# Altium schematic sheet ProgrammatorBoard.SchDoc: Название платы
size 209 x 297 mm; ApprovedBy: Рогов; CheckedBy: Фамилия проверяющего; DrawnBy: Фамилия разработчика; DocumentNumber: Введите номер платы + Э3; SheetNumber: пусто если всего 1, в остальных случаях 1; SheetTotal: количество листов; PageSetup: Record=PageOptions¦CenterHorizontal=True¦CenterVertical=True¦PrintScale=0.94¦XCorrection=1.00¦YCorrection=1.00¦PrintKind=2¦BorderSize=5000000¦LeftOffset=0¦BottomOffset=0¦Orientation=1¦PaperLength=2970¦PaperWidth=2100¦Scale=100¦PaperSource=7¦PrintQuality=600¦MediaType=1¦DitherType=10¦PaperKind=A4¦PrintScaleMode=1; Title1str: (вторая строка при необходимости); DocumentType: Тип схемы; Format: A4
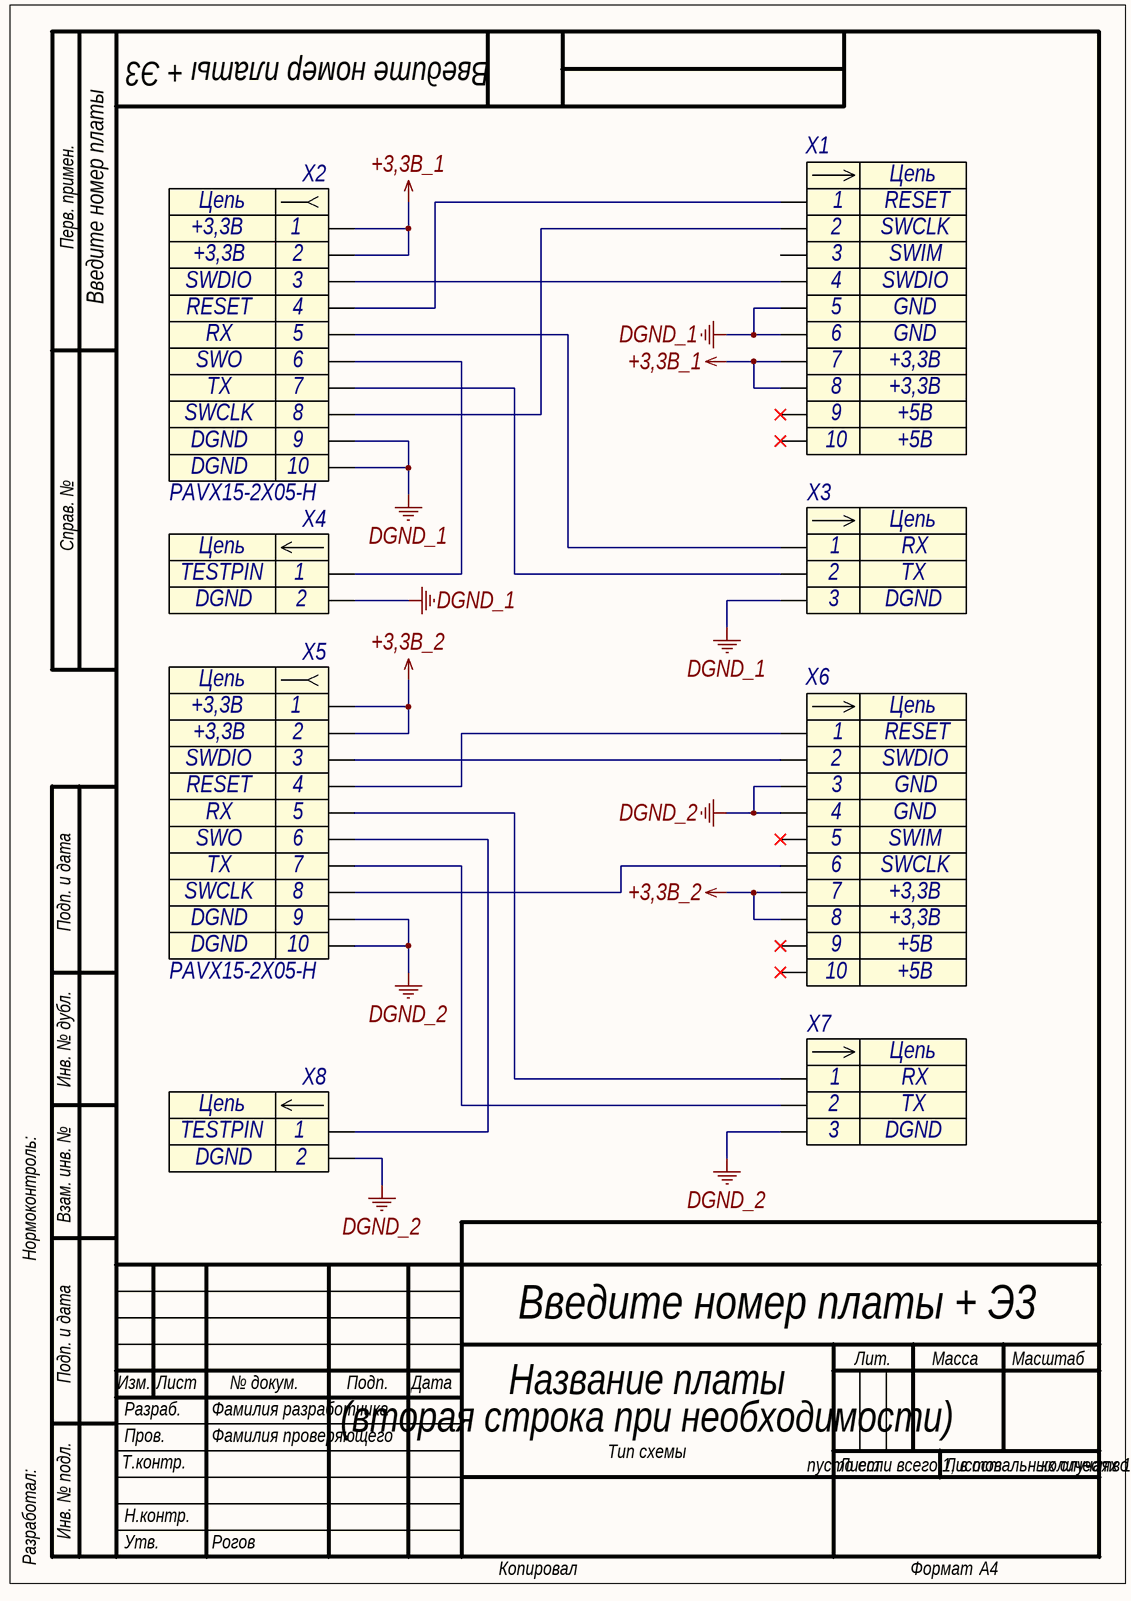
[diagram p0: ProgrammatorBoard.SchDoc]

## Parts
X1  Header_10_plg  [IDC-10MS]  (value not drawn)
X2  Header_10_sct  [PAVX15-2X05-H]  (value not drawn)
X3  Header_3_plg  [PLS-3]  (value not drawn)
X4  (no value)  [PLS-2]
X5  Header_10_sct  [PAVX15-2X05-H]  (value not drawn)
X6  Header_10_plg  [IDC-10MS]  (value not drawn)
X7  Header_3_plg  [PLS-3]  (value not drawn)
X8  (no value)  [PLS-2]

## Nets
+3,3B_1: X1.7 X1.8 X2.1 X2.2
+3,3B_2: X5.1 X5.2 X6.7 X6.8
DGND_1: X1.5 X1.6 X2.9 X2.10 X3.3 X4.2
DGND_2: X5.9 X5.10 X6.3 X6.4 X7.3 X8.2
NetX1_1: X1.1 X2.4
NetX1_2: X1.2 X2.8
NetX1_4: X1.4 X2.3
NetX2_5: X2.5 X3.1
NetX2_6: X2.6 X4.1
NetX2_7: X2.7 X3.2
NetX5_3: X5.3 X6.2
NetX5_4: X5.4 X6.1
NetX5_5: X5.5 X7.1
NetX5_6: X5.6 X8.1
NetX5_7: X5.7 X7.2
NetX5_8: X5.8 X6.6

Not connected (* = marked no-connect by the designer): X1 3 9* 10*; X6 5* 9* 10*

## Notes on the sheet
- Перв. примен.
- Справ. №
- Подп. и дата
- Инв. № дубл.
- Нормоконтроль:
- Взам. инв. №
- Изм.
- Лист
- № докум.
- Подп.
- Дата
- Лит.
- Масса
- Масштаб
- Т.контр.
- Пров.
- Разраб.
- Листов
- Разработал:
- Инв. № подл.
- Н.контр.
- Утв.
- Копировал
- Формат

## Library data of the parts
X1 = connect200: Разъем - 10 конт. вилка; Part Name: BH-10 вилка; Part Number: DS1013-10SSiB1-B-0; Manufacture: Connfly electronic; Contact_1: RESET; Contact_2: SWCLK; Contact_3: SWIM; Contact_4: SWDIO; Contact_5: GND; Etch: 2.54mm; Contact_7: +3,3B; Contact_9: +5B
X2 X5 = connect107: Разъем - 10 конт. розетка; Part Name: Штыри двухрядные 2x5; Manufacture: Auk Contractors; Contact_1: +3,3B; Contact_3: SWDIO; Contact_4: RESET; Contact_5: RX; Contact_6: SWO; Etch: 1.27mm; Contact_7: TX; Contact_8: SWCLK; Contact_9: DGND
X3 X7 = connect33: Разъем - 3 конт. вилка; Part Number: DS1021-1*3SF112-B; Manufacture: Ningbo connfly electronic; Contact_1: RX; Contact_2: TX; Contact_3: DGND; Etch: 2,54mm
X4 X8 = connect159: Разъем - 2 конт. вилка; Contact_1: TESTPIN; Contact_2: DGND; Etch: 2,54mm
X6 = connect200: Разъем - 10 конт. вилка; Part Name: BH-10 вилка; Part Number: DS1013-10SSiB1-B-0; Manufacture: Connfly electronic; Contact_1: RESET; Contact_2: SWDIO; Contact_3: GND; Contact_5: SWIM; Contact_6: SWCLK; Etch: 2.54mm; Contact_7: +3,3B; Contact_9: +5B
